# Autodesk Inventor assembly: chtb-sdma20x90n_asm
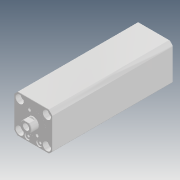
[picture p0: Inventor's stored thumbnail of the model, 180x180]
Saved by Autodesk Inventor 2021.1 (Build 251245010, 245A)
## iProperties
Created: 2018-05
Part Number: chtb-sdma20x90n_asm
Description: STEP AP214
Document SubType Name: Assembly
Designer: user
Title: chtb-sdma20x90n_asm.STEP
Revision Number: ÈÎºÎ
Sending System: SolidWorks 2016
Preprocessor: SwSTEP 2.0
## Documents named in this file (4)
- D:\Vault_2016\Projekty\Clamptek\Hydraulic\CHTB\CHTB-20\Inventor\CHTB-SDMA20x90N\chtb-sdma20x90n_asm.iam
- D:\Vault_2016\Projekty\Clamptek\Hydraulic\CHTB\CHTB-20\Inventor\CHTB-SDMA20x90N\CHTB-SDMA20X90NBT.ipt
- D:\Vault_2016\Projekty\Clamptek\Hydraulic\CHTB\CHTB-20\Inventor\CHTB-SDMA20x90N\CHTB-SDMA20X90NHSG.ipt
- D:\Vault_2016\Projekty\Clamptek\Hydraulic\CHTB\CHTB-20\Inventor\CHTB-SDMA20x90N\QG_3.ipt
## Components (3 placed, 3 different names)
1. CHTB-SDMA20X90NBT_1
2. CHTB-SDMA20X90NHSG_2
3. QG_3_3
